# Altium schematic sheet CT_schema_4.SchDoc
size 297 x 173 mm
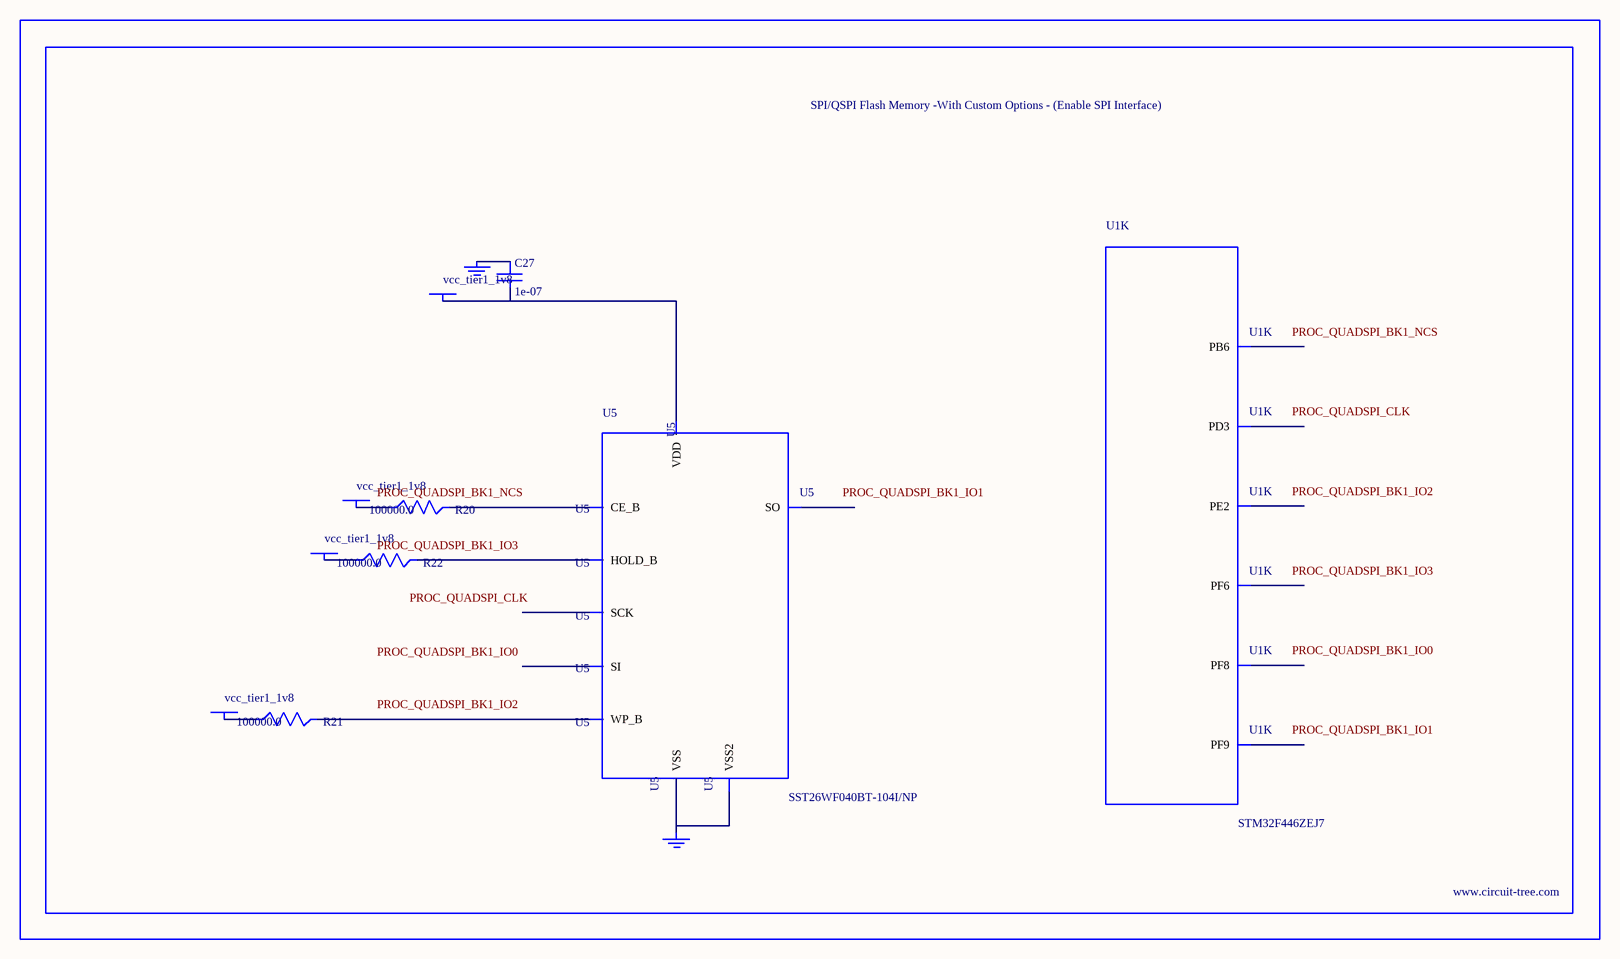
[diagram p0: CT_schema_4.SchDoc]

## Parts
BORDER3  (no value)
C27  1e-07  [C0402]
GND_INSTANCE_3_0  (no value)
GND_INSTANCE_3_1  (no value)
POWER_INSTANCE_3_0  vcc_tier1_1v8
POWER_INSTANCE_3_1  vcc_tier1_1v8
POWER_INSTANCE_3_2  vcc_tier1_1v8
POWER_INSTANCE_3_3  vcc_tier1_1v8
R20  100000.0  [R0603]
R21  100000.0  [R0603]
R22  100000.0  [R0603]
U1  STM32F446ZEJ7  [UFBGA144]  (part K of 12)
U5  SST26WF040BT-104I/NP  [USON-8]

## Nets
NetC27_1: C27.1 GND_INSTANCE_3_0.0(GND)
NetC27_2: C27.2 POWER_INSTANCE_3_3.0(PWR) U5.8(VDD)
NetGND_INSTANCE_3_1_0: GND_INSTANCE_3_1.0(GND) U5.4(VSS) U5.9(VSS2)
NetPOWER_INSTANCE_3_0_0: POWER_INSTANCE_3_0.0(PWR) R20.1
NetPOWER_INSTANCE_3_1_0: POWER_INSTANCE_3_1.0(PWR) R21.1
NetPOWER_INSTANCE_3_2_0: POWER_INSTANCE_3_2.0(PWR) R22.1
NetR20_2: R20.2 U5.1(CE_B)
NetR21_2: R21.2 U5.3(WP_B)
NetR22_2: R22.2 U5.7(HOLD_B)

Not connected (* = marked no-connect by the designer): U1 A3(PE2) C6(PB6) D9(PD3) F3(PF6) G2(PF9) G3(PF8); U5 2(SO) 5(SI) 6(SCK)

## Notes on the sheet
- Labels drawn without touching a wire or pin: PROC_QUADSPI_BK1_IO0, PROC_QUADSPI_BK1_IO1, PROC_QUADSPI_BK1_IO2, PROC_QUADSPI_BK1_IO3, PROC_QUADSPI_BK1_NCS, PROC_QUADSPI_CLK

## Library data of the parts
BORDER3 = BORDER_PAGE3
C27 = C0402C104K3RACTU
GND_INSTANCE_3_0 GND_INSTANCE_3_1 = GND
POWER_INSTANCE_3_0-POWER_INSTANCE_3_3 = PWR
R20-R22 = RC0603JR-07100KL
